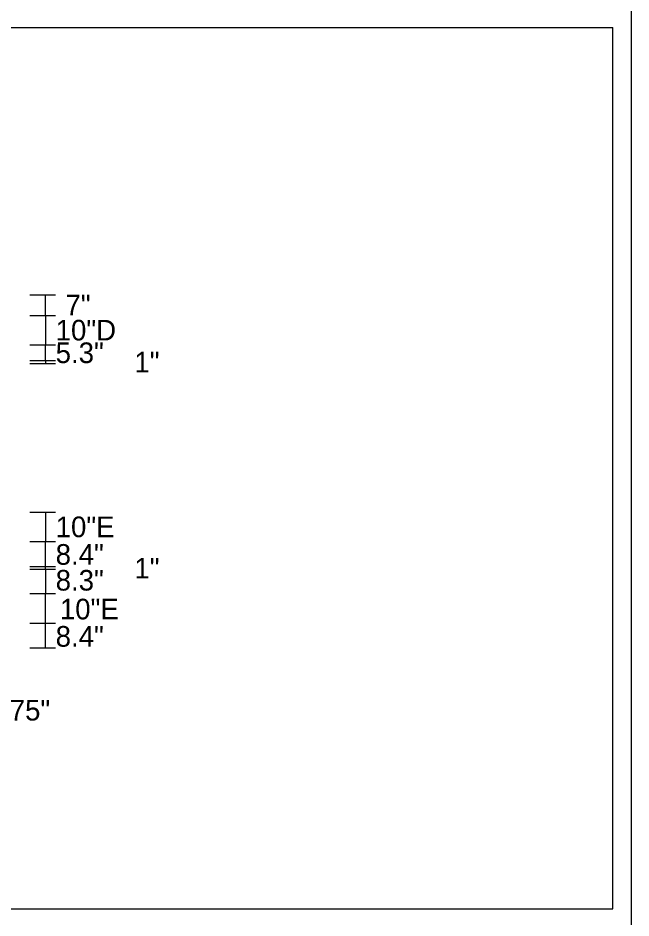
# Model space of a CAD drawing. Extents: x 17890071 to 17890754, y 17897628 to 17897992.
# Drawn here: x 17890134.54 to 17890151.87, y 17897796.89 to 17897822.34 of the extents above; entities that cross this region are included whole.
import ezdxf

# ---------------------------------------------------------------- set-up
doc = ezdxf.new("R2010")
doc.units = 0
doc.layers.add('GSDims', color=7, linetype='Continuous')
doc.layers.add('SheetLinesMisc2_dp', color=7, linetype='Continuous')

msp = doc.modelspace()

# ---------------------------------------------------------------- linework, layer by layer
at = {"layer": 'GSDims'}
for p, q in [((17890134.877, 17897814.514), (17890135.606, 17897814.514)), ((17890135.314, 17897813.927), (17890135.314, 17897814.514)), ((17890134.877, 17897813.927), (17890135.606, 17897813.927)), ((17890134.877, 17897813.927), (17890135.606, 17897813.927)), ((17890135.314, 17897813.927), (17890135.314, 17897813.094)), ((17890134.877, 17897813.094), (17890135.606, 17897813.094)), ((17890134.877, 17897813.094), (17890135.606, 17897813.094)), ((17890135.314, 17897812.649), (17890135.314, 17897813.094)), ((17890134.877, 17897812.649), (17890135.606, 17897812.649)), ((17890134.877, 17897812.649), (17890135.606, 17897812.649)), ((17890135.314, 17897812.649), (17890135.314, 17897812.566)), ((17890134.877, 17897812.566), (17890135.606, 17897812.566)), ((17890134.877, 17897812.566), (17890135.606, 17897812.566)), ((17890134.877, 17897808.366), (17890135.606, 17897808.366)), ((17890134.877, 17897808.366), (17890135.606, 17897808.366)), ((17890135.314, 17897808.366), (17890135.314, 17897807.532)), ((17890134.877, 17897807.532), (17890135.606, 17897807.532)), ((17890134.877, 17897807.532), (17890135.606, 17897807.532)), ((17890135.314, 17897806.832), (17890135.314, 17897807.532)), ((17890134.877, 17897806.832), (17890135.606, 17897806.832)), ((17890134.877, 17897806.832), (17890135.606, 17897806.832)), ((17890134.877, 17897806.749), (17890135.606, 17897806.749)), ((17890134.877, 17897806.749), (17890135.606, 17897806.749)), ((17890135.314, 17897806.749), (17890135.314, 17897806.832)), ((17890135.314, 17897806.749), (17890135.314, 17897806.061)), ((17890134.877, 17897806.061), (17890135.606, 17897806.061)), ((17890135.314, 17897805.228), (17890135.314, 17897806.061)), ((17890134.877, 17897805.228), (17890135.606, 17897805.228)), ((17890135.314, 17897804.529), (17890135.314, 17897805.228)), ((17890134.877, 17897804.529), (17890135.606, 17897804.529))]:
    msp.add_line(p, q, dxfattribs=at)
at = {"layer": 'SheetLinesMisc2_dp'}
for p, q in [((17890151.871, 17897869.435), (17890151.871, 17897775.777)), ((17890100.188, 17897822.069), (17890151.359, 17897822.069)), ((17890151.359, 17897797.179), (17890151.359, 17897822.071)), ((17890100.188, 17897797.144), (17890151.359, 17897797.144)), ((17890151.359, 17897797.146), (17890151.359, 17897797.179))]:
    msp.add_line(p, q, dxfattribs=at)

# ---------------------------------------------------------------- texts
at = {"layer": 'GSDims'}
for s, p in [('7"', (17890135.883, 17897813.929)), ('10"D', (17890135.606, 17897813.219)), ('5.3"', (17890135.606, 17897812.58)), ('1"', (17890137.832, 17897812.316)), ('10"E', (17890135.606, 17897807.657)), ('8.4"', (17890135.606, 17897806.877)), ('1"', (17890137.832, 17897806.489)), ('8.3"', (17890135.606, 17897806.147)), ('10"E', (17890135.725, 17897805.332)), ('8.4"', (17890135.606, 17897804.56)), ('1.75"', (17890133.657, 17897802.472))]:
    msp.add_text(s, height=0.5833, dxfattribs=at).set_placement(p)

doc.saveas('drawing.dxf')
